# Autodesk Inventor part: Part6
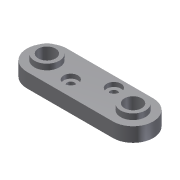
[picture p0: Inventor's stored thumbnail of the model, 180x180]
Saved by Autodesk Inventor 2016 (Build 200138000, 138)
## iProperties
Shininess: 77.0
Length Units: 11269
Angle Units: 11279
Time Units: 11290
Mass Units: 11283
Length Display Precision: 3
Angle Display Precision: 2
Created: 2002-01
Part Number: Part6
Document SubType Name: Modeling
Designer: ***
Density: 1 g/cm^3
Mass: 21.6911 g
Surface Area: 77.1136 cm^2
Volume: 21.6911 cm^3
Material: Generic
Appearance: Default
Density: 0.0
Volumn: 0.0
Area: 0.0
PropertySet Name: Model Information
Control State: 0
Master: False
Checked Out: False
Author: ***
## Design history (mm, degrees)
sketch "Sketch1"
  geometry: L1 (-33.118, 12.346)-(26.882, 12.361); L2 (-33.111, -15.654)-(26.889, -15.639); C1 r 6 at (-33.114, -1.654); C2 r 6 at (26.886, -1.639); A1 r 14 centre (-33.114, -1.654) between (-33.118, 12.346) and (-33.111, -15.654); A2 r 14 centre (26.886, -1.639) between (26.889, -15.639) and (26.882, 12.361)
  constraints: 4 centre point, 4 end point, 4 point on circle, 4 tangent, 2 coincident, 2 equal radius
  dimensions: "d0" = 60 distance of L1.start L1.end; "d1" = 14 radius of A1; "d2" = 12 diameter of C1
extrude "Extrusion1" new body sketch "Sketch1" distance "d3" = 10; taper "d4" = 0 deg
sketch "Sketch2"
  geometry: C1 r 6 at (26.886, -1.639) reference; C2 r 6 at (-33.114, -1.654) reference; C3 r 8.694 at (-33.114, -1.654); C4 r 8.694 at (26.886, -1.639)
  constraints: 2 centre point, 2 coincident, 1 equal radius
extrude "Extrusion2" join sketch "Sketch2" distance "d5" = 4; taper "d6" = 0 deg
sketch "Sketch3"
  geometry: C1 r 8.694 at (-33.114, -1.654) reference; C2 r 8.694 at (26.886, -1.639) reference; 3 further points
  dimensions: "d7" = 20 horizontal distance of C1.centre point (-13.114, -5); "d8" = 20 horizontal distance of C2.centre point (6.886, 5); "d9" = 5 vertical distance of point (0, 0) point (6.886, 5); "d10" = 5 vertical distance of point (-13.114, -5) point (0, 0)
hole "Hole1" sketch "Sketch3" at (-13.114, -5), (6.886, 5) diameter "d11" = 5; stored, may be unused: countersink angle "d15" = 90 deg, drill point angle "d17" = 0 deg; dims "d12" = 6, "d13" = 10, "d14" = 3, "d16" = 8
body "Solid1"
